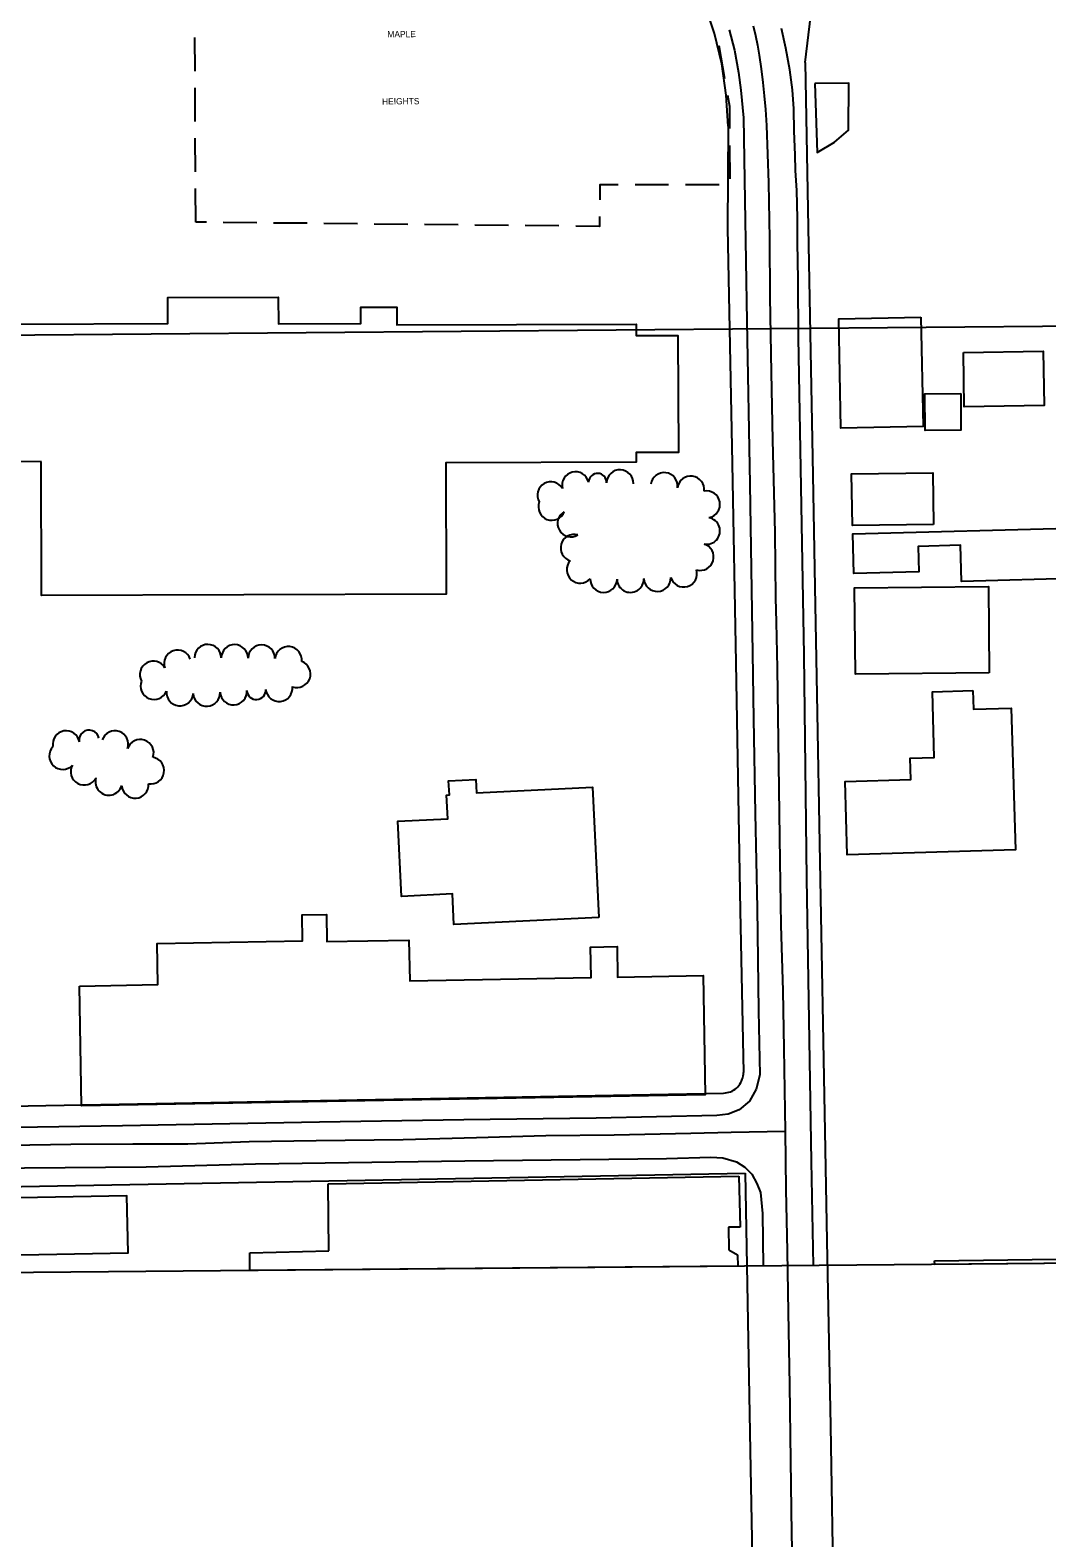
# Model space of a CAD drawing. Extents: x -2233 to 187241, y 4582 to 150524.
# Drawn here: x 118093 to 118851, y 57219 to 58341 of the extents above; entities that cross this region are included whole.
import ezdxf

# ---------------------------------------------------------------- set-up
doc = ezdxf.new("R2010")
doc.units = 0
for name, color, linetype in [('60', 7, 'Continuous'), ('BLDG', 7, 'Continuous'), ('CITY-NAME', 7, 'Continuous'), ('GE_X_CL_2000', 7, 'Continuous'), ('GRID', 7, 'Continuous'), ('RECREATION', 7, 'Continuous'), ('ROAD', 7, 'Continuous'), ('RW_X_Fee_RW', 7, 'Continuous'), ('TREES', 7, 'Continuous')]:
    doc.layers.add(name, color=color, linetype=linetype)

msp = doc.modelspace()

# ---------------------------------------------------------------- linework, layer by layer
at = {"layer": '60'}
msp.add_line((120014.2, 57433.2), (115014.4, 57389.6), dxfattribs=at)
at = {"layer": 'BLDG'}
for p, q in [((118315.3, 57482.5), (118621.2, 57488.2)), ((118315.9, 57432.4), (118315.3, 57482.5)), ((118621.2, 57488.2), (118622.2, 57450.2)), ((118622.2, 57450.2), (118613.6, 57450.2)), ((118613.6, 57450.2), (118613.8, 57433.2)), ((118257, 57431.1), (118315.9, 57432.4)), ((118257.1, 57417.9), (118257, 57431.1)), ((118613.8, 57433.2), (118620.3, 57429.6)), ((118620.3, 57429.6), (118620.4, 57421)), ((118767.1, 57425), (118919.2, 57427.3)), ((118767.2, 57422.3), (118767.1, 57425)), ((118620.4, 57421), (118257.1, 57417.9)), ((118919.3, 57423.6), (118767.2, 57422.3))]:
    msp.add_line(p, q, dxfattribs=at)
for points in [[(118677.8, 58301.6), (118679.7, 58250.1), (118692.6, 58257.9), (118702.9, 58266.8), (118703.1, 58301.8)], [(118101.5, 58020.1), (117841.9, 58019.1), (117841.5, 58122.7), (117980.4, 58123.2), (117980.3, 58154), (118085.3, 58154.3), (118085.4, 58122.4), (118195.8, 58122.8), (118195.8, 58142.3), (118278.2, 58142.6), (118278.3, 58122.6), (118339.8, 58122.8), (118339.8, 58135), (118366.6, 58135.1), (118366.6, 58121.8), (118544.8, 58122.5), (118544.8, 58113.9), (118575.8, 58114), (118576.2, 58026.9), (118544.7, 58026.8), (118544.7, 58019.7), (118402.9, 58019.2), (118403.3, 57921.5), (118101.9, 57920.4)], [(118756.9, 58127.6), (118758.5, 58046.2), (118697.3, 58045), (118695.7, 58126.4)], [(118788.5, 58101.4), (118848, 58102.4), (118848.6, 58061.8), (118789.1, 58060.8)], [(118786.5, 58070.7), (118786.7, 58043.6), (118760.1, 58043.3), (118759.9, 58070.5)], [(118766.3, 57973.2), (118705.8, 57972.4), (118705.2, 58010.9), (118765.8, 58011.7)], [(118877.3, 57933.2), (118787.1, 57930.7), (118786.4, 57957.8), (118754.7, 57957), (118755.2, 57938), (118707, 57936.7), (118706.2, 57966.2), (118876.3, 57970.8)], [(118807.8, 57862.8), (118708.1, 57861.9), (118707.5, 57926.1), (118807.2, 57927)], [(118795.6, 57849.6), (118796.1, 57835.8), (118824.2, 57836.6), (118827.3, 57731), (118702, 57727.3), (118700.4, 57782), (118749.3, 57783.4), (118748.8, 57799.3), (118766.8, 57799.8), (118765.4, 57848.7)], [(118517, 57680.6), (118409, 57675.4), (118407.9, 57698.2), (118370, 57696.3), (118367.2, 57752.3), (118404.4, 57754.1), (118403.6, 57771.8), (118405.6, 57771.9), (118405.1, 57782.5), (118425.3, 57783.5), (118425.8, 57773.5), (118512.2, 57777.7)], [(118130.1, 57629.6), (118188.5, 57630.7), (118187.9, 57661.3), (118296.2, 57663.2), (118295.9, 57682.7), (118314, 57683), (118314.3, 57662.8), (118375.5, 57663.9), (118376.1, 57633.5), (118511.2, 57635.9), (118510.8, 57658.7), (118530.5, 57659.1), (118530.9, 57636.3), (118594.6, 57637.4), (118596.2, 57548.6), (118131.7, 57540.4)], [(118006.4, 57428.1), (118166.3, 57431), (118165.5, 57473.4), (118005.6, 57470.5)]]:
    msp.add_lwpolyline(points, close=True, dxfattribs=at)
at = {"layer": 'GE_X_CL_2000'}
for points in [[(118632, 58344.4), (118633.7, 58337.2), (118635.1, 58330), (118636.3, 58322.6), (118637.8, 58312.5), (118639.1, 58302.4), (118640.2, 58292.3), (118641.1, 58282.1), (118641.8, 58270.4), (118643.3, 58227.5), (118644.1, 58186), (118644.3, 58142.7), (118645.3, 58086.4), (118646.2, 58036), (118648, 57967.3), (118648.6, 57918.7), (118649, 57900.5), (118649.8, 57866.4), (118651.7, 57722.6), (118652.5, 57674.9), (118653.9, 57626.2), (118654.7, 57583.2), (118655.8, 57521.6)], [(117571.6, 57502.6), (117583, 57502.3), (117682.4, 57504.5), (117808.4, 57505.9), (117903.4, 57507.4), (117947.1, 57508.2), (118005, 57509.4), (118078.1, 57511.2), (118123.7, 57511.9), (118169.9, 57512.3), (118210.7, 57512.3), (118256.4, 57513.9), (118306.3, 57514.7), (118371.2, 57515.4), (118425.9, 57516.9), (118477.4, 57518.5), (118528.5, 57518.9), (118585.4, 57520), (118615.6, 57520.8), (118655.8, 57521.6)], [(118655.8, 57521.6), (118656.3, 57478.1), (118657.3, 57432.3), (118658, 57386.9), (118659, 57332.4), (118659.8, 57276.4), (118660.5, 57222.1), (118661.6, 57166.5), (118662.6, 57110.4), (118663.5, 57053.5), (118664.5, 57005.3), (118665, 56967.9), (118665.9, 56923.2), (118666.8, 56874.3), (118668.2, 56825.2), (118669.2, 56782.7), (118670.6, 56709.7)]]:
    msp.add_lwpolyline(points, dxfattribs=at)
at = {"layer": 'GRID'}
msp.add_line((120008.2, 58130.9), (115008.3, 58087.3), dxfattribs=at)
at = {"layer": 'RECREATION'}
for p, q in [((118216.2, 58310.8), (118216.1, 58335.8)), ((118606.3, 58329.9), (118610.6, 58305.2)), ((118216.4, 58273.3), (118216.3, 58298.3)), ((118216.6, 58235.8), (118216.4, 58260.8)), ((118614.4, 58255.5), (118614.6, 58230.5)), ((118216.8, 58198.3), (118216.6, 58223.3)), ((118568.9, 58226.2), (118543.9, 58226.2)), ((118606.5, 58226.2), (118581.4, 58226.2)), ((118224.7, 58198.3), (118216.8, 58198.3)), ((118262.2, 58197.9), (118237.2, 58198.1)), ((118299.7, 58197.5), (118274.7, 58197.7)), ((118337.2, 58197.1), (118312.2, 58197.3)), ((118374.7, 58196.7), (118349.7, 58196.9)), ((118412.2, 58196.3), (118387.2, 58196.6)), ((118449.7, 58195.9), (118424.7, 58196.2)), ((118487.2, 58195.5), (118462.2, 58195.8))]:
    msp.add_line(p, q, dxfattribs=at)
for points in [[(118612.8, 58292.9), (118614.2, 58284.8), (118614.3, 58268)], [(118531.4, 58226.2), (118517.7, 58226.2), (118517.6, 58215)], [(118517.4, 58202.5), (118517.4, 58195.2), (118499.7, 58195.4)]]:
    msp.add_lwpolyline(points, dxfattribs=at)
at = {"layer": 'ROAD'}
for points in [[(118614, 58341.6), (118618, 58326.3), (118621.1, 58309.8), (118622.8, 58296.6), (118624.8, 58275.9), (118625.8, 58214.7), (118627.2, 58124.4), (118629.5, 58003.4), (118631.5, 57877.4), (118632.2, 57828.7), (118633.5, 57758.1), (118634.9, 57687.7), (118635.9, 57611.1), (118636.9, 57563.5), (118634.1, 57552.9), (118629.2, 57543.9), (118621.5, 57537.6), (118613.3, 57534.2), (118604.9, 57533.2), (118514.9, 57531.4), (118416.3, 57530.1)], [(118662.4, 58266.2), (118662.2, 58282.8), (118661.2, 58296.9), (118659.2, 58311.7), (118656.2, 58327.8), (118653, 58342.5)], [(118676.9, 57421.5), (118675.4, 57499.1), (118672, 57709.6), (118669.9, 57876.1), (118665.7, 58112.4), (118665.5, 58155.4), (118664.9, 58183.5), (118664.9, 58201.3), (118664.5, 58221.9), (118663.5, 58236.7), (118663.2, 58248.5), (118662.4, 58266.2)], [(118416.3, 57530.1), (118309, 57528.2), (118162.1, 57525.7), (117987.6, 57522.9)], [(117455.8, 57410.9), (117457.2, 57413.9), (117465.6, 57426.5), (117475.8, 57438.6), (117486.1, 57449.7), (117499.9, 57460.3), (117513.7, 57468.4), (117527.6, 57475.1), (117543.5, 57480.4), (117559.2, 57483.6), (117577.9, 57485), (117612.2, 57485.9), (117667.2, 57486.5), (117753.4, 57488.3), (117811.4, 57489.2), (117889.1, 57490.2), (117955.5, 57491.8), (118015.9, 57492.7), (118089.1, 57494.3), (118179.7, 57495), (118261.3, 57497.2), (118417.1, 57499.5)], [(118417.1, 57499.5), (118567.3, 57501.2), (118600.4, 57502.3), (118609.2, 57501.7), (118619.4, 57498.8), (118625.7, 57494.9), (118630.9, 57489.6), (118634.6, 57482.7), (118637.4, 57476), (118638.8, 57460.3), (118639.3, 57421.2)]]:
    msp.add_lwpolyline(points, dxfattribs=at)
at = {"layer": 'RW_X_Fee_RW'}
for p, q in [((118670.6, 58317.2), (118701.6, 58569.3)), ((118613.4, 58269.7), (118612.9, 58193.9)), ((118681.6, 57722.1), (118685.4, 57521.7))]:
    msp.add_line(p, q, dxfattribs=at)
for points in [[(118613.4, 58269.7), (118611.9, 58293), (118608.5, 58316.2), (118603.1, 58338.9), (118595.7, 58361.2), (118586.4, 58382.7), (118575.4, 58403.3), (118562.6, 58422.9), (118548.1, 58441.3), (118532.2, 58458.4), (118514.8, 58474), (118496.1, 58488.1), (118491.6, 58490.9), (118476.3, 58500.6), (118455.5, 58511.3), (118433.8, 58520.2), (118411.4, 58527.1), (118408.6, 58527.7), (118388.6, 58532.1), (118365.4, 58535.2), (118342, 58536.2)], [(118670.6, 58317.2), (118672.9, 58194.4), (118675.8, 58036.6), (118676.3, 58010.1)], [(118612.9, 58193.9), (118616.2, 58018.6), (118618.9, 57870.2), (118622.3, 57685.8), (118624.6, 57565.3)], [(118676.3, 58010.1), (118677.1, 57968.6), (118677.8, 57926.6), (118679.3, 57846.6), (118681.6, 57722.1)], [(118609.9, 57550), (118611.2, 57550.1), (118612.5, 57550.3), (118613.7, 57550.6), (118615, 57551), (118616.2, 57551.5), (118617.3, 57552.2), (118618.4, 57552.9), (118619.4, 57553.7), (118620.4, 57554.6), (118621.3, 57555.6), (118622, 57556.6), (118622.7, 57557.8), (118623.3, 57558.9), (118623.8, 57560.2), (118624.1, 57561.4), (118624.4, 57562.7), (118624.6, 57564), (118624.6, 57565.3)], [(117574.9, 57530.8), (117906.2, 57537), (117941.3, 57537.6), (118038.8, 57539.4), (118105.1, 57540.7), (118609.9, 57550)], [(118685.4, 57521.7), (118686.9, 57440), (118689.5, 57302.2), (118690.3, 57257.2), (118691.1, 57212.2), (118693, 57112.2), (118693.6, 57079.2), (118695.6, 56972.2), (118698, 56842.5)], [(117576, 57470.8), (117664.5, 57472.5), (117929.5, 57477.4), (117965.2, 57478.1), (118626, 57490.3)], [(118626, 57490.3), (118629.8, 57283.5), (118632.9, 57113.5), (118633.5, 57080.5), (118635.8, 56960.5), (118637.6, 56858.3), (118638.2, 56841.5)]]:
    msp.add_lwpolyline(points, dxfattribs=at)
at = {"layer": 'TREES'}
for centre, radius, start, end in [((118499.6, 58002.5), 10, 13.9408, 193.9408), ((118516, 58004.6), 6.72, 357.922, 177.922), ((118532.7, 58004), 10, 357.922, 177.922), ((118565.6, 58001.9), 10, 352.5382, 172.5382), ((118585.4, 57999.3), 10, 352.5382, 172.5382), ((118481.2, 57995.1), 10, 30.0489, 210.0489), ((118597.2, 57988.2), 10, 280.7518, 100.7518), ((118481.9, 57986.4), 10, 158.6279, 338.6279), ((118496.2, 57974.1), 10, 120.272, 300.272), ((118597.2, 57968.5), 10, 259.0229, 79.0229), ((118498.5, 57955.9), 10, 73.6035, 253.6035), ((118592.5, 57949.1), 10, 253.7672, 73.7672), ((118503.1, 57939.6), 10, 138.133, 318.133), ((118520.5, 57932.7), 10, 178.7621, 358.7621), ((118540.5, 57932.7), 10, 181.1897, 1.1897), ((118560.5, 57933.4), 10, 182.67, 2.67), ((118580.1, 57936.7), 10, 196.4117, 16.4117), ((118203.2, 57869.8), 10, 19.0904, 199.0904), ((118225.7, 57874), 10, 359.3672, 179.3672), ((118245.7, 57873.8), 10, 359.3672, 179.3672), ((118265.7, 57873.6), 10, 359.3672, 179.3672), ((118285.7, 57872.4), 10, 353.8719, 173.8719), ((118185.1, 57861.6), 10, 29.4298, 209.4298), ((118292.2, 57861.9), 10, 249.8786, 69.8786), ((118185.6, 57853), 10, 158.2091, 338.2091), ((118278.8, 57851.5), 10, 186.0234, 6.0234), ((118204.9, 57848.3), 10, 174.3685, 354.3685), ((118224.8, 57847.9), 10, 183.3323, 3.3323), ((118244.8, 57849), 10, 183.3323, 3.3323), ((118261.8, 57850), 7.07, 183.3323, 3.3323), ((118120.2, 57809.7), 10, 10.5827, 190.5827), ((118137.3, 57812.8), 7.42, 9.9343, 189.9343), ((118156.5, 57809.7), 10, 341.0853, 161.0853), ((118117.6, 57800.9), 10, 136.5491, 316.5491), ((118175.4, 57803.2), 10, 341.0853, 161.0853), ((118183.2, 57790.1), 10, 260.3535, 80.3535), ((118133.6, 57789.3), 10, 151.4281, 331.4281), ((118152, 57781.7), 10, 163.5085, 343.5085), ((118171.6, 57779.5), 10, 184.1106, 4.1106)]:
    msp.add_arc(centre, radius, start, end, dxfattribs=at)

# ---------------------------------------------------------------- texts
at = {"layer": 'CITY-NAME'}
for s, p in [('MAPLE', (118359.5, 58335.9)), ('HEIGHTS', (118355.5, 58285.9))]:
    msp.add_text(s, height=4.68, rotation=0.5, dxfattribs=at).set_placement(p)

doc.saveas('drawing.dxf')
